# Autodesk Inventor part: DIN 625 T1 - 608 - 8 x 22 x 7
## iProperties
Library Location: C:\Program Files\Autodesk\Inventor 6\content
Library: local
SubLibrary: DIN
Family: 249
Member: 20
Member Major Revision: 1
Member Minor Revision: 1
Comments: To add or edit properties for Autodesk Inventor files, use iProperties.
Created: 2003-05
Part Number: DIN 625 T1 - 608 - 8 x 22 x 7
Vendor: Autodesk Inc.
Document SubType Name: Modeling
Designer: Philippe
Description: Roulement rainuré à billes
Standard: DIN 625 T1 608 - 8 x 22 x 7
Alert: To add or edit properties for Autodesk Inventor files, use iProperties.
Control State: 0
Master: False
Checked Out: False
Shininess: 64.0
Length Units: 11269
Angle Units: 11279
Time Units: 11290
Mass Units: 11283
Length Display Precision: 3
Angle Display Precision: 2
Compacted: True
Classification: un/spsc 31171504
Density: 0.0
Volumn: 0.0
Area: 0.0
PropertySet Name: Model Information
Author: Philippe
Revision Number: 1
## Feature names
1. Corps [Revolution]
2. Congé1 [Fillet]
3. Sphère [Revolution]
4. Sphères [Circular Pattern]
